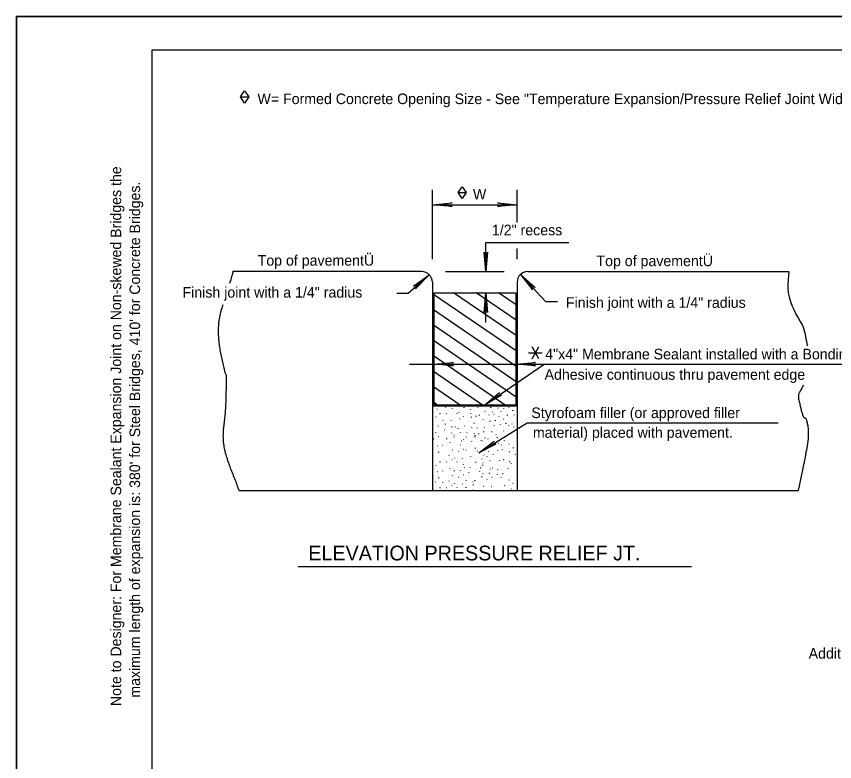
# Model space of a CAD drawing. Extents: x 1000 to 1036, y 1000 to 1022.7.
# Drawn here: x 1000 to 1012.07, y 1011 to 1022 of the extents above; entities that cross this region are included whole.
import ezdxf

# ---------------------------------------------------------------- set-up
doc = ezdxf.new("R2010")
doc.units = 0
for name, color, linetype in [('KS_Borders_Z_N', 7, 'Continuous'), ('KS_PlotShape_z_e', 7, 'Continuous'), ('rd_Detail Annotation_z_n', 7, 'Continuous'), ('rd_Details_z_n', 7, 'Continuous'), ('rd_Dimensions_z_n', 7, 'Continuous'), ('rd_Misc Label_z_n', 7, 'Continuous'), ('rd_Symbols_z_n', 7, 'Continuous')]:
    doc.layers.add(name, color=color, linetype=linetype)

msp = doc.modelspace()

# ---------------------------------------------------------------- linework, layer by layer
at = {"layer": 'KS_Borders_Z_N'}
for points in [[(999.998, 1021.998), (1035.998, 1021.998), (1035.998, 999.998), (999.998, 999.998)], [(1001.998, 1000.498), (1035.498, 1000.498), (1035.498, 1021.498), (1001.998, 1021.498)]]:
    msp.add_lwpolyline(points, close=True, dxfattribs=at)
at = {"layer": 'KS_PlotShape_z_e'}
msp.add_lwpolyline([(999.998, 999.998), (1035.998, 999.998), (1035.998, 1021.998), (999.998, 1021.998)], close=True, dxfattribs=at)
at = {"layer": 'rd_Detail Annotation_z_n'}
for p, q in [((1005.781, 1017.91), (1006.092, 1018.184)), ((1007.806, 1017.791), (1007.438, 1018.189)), ((1005.801, 1016.866), (1012.902, 1016.866)), ((1006.824, 1015.558), (1007.538, 1016)), ((1007.538, 1016), (1011.238, 1016)), ((1004.156, 1013.88), (1009.961, 1013.88))]:
    msp.add_line(p, q, dxfattribs=at)
at = {"layer": 'rd_Details_z_n'}
for p, q in [((1005.981, 1018.23), (1003.195, 1018.23)), ((1007.544, 1018.23), (1011.399, 1018.23)), ((1006.137, 1018.074), (1006.137, 1014.999)), ((1007.387, 1018.074), (1007.387, 1014.999)), ((1007.387, 1017.049), (1006.137, 1017.904)), ((1006.16, 1017.918), (1007.371, 1017.918)), ((1006.16, 1017.918), (1006.16, 1016.266)), ((1007.387, 1017.277), (1006.45, 1017.918)), ((1007.387, 1017.504), (1006.782, 1017.918)), ((1007.387, 1017.731), (1007.114, 1017.918)), ((1007.371, 1017.918), (1007.371, 1016.266)), ((1007.387, 1016.822), (1006.137, 1017.677)), ((1007.387, 1016.595), (1006.137, 1017.45)), ((1007.387, 1016.368), (1006.137, 1017.223)), ((1007.226, 1016.251), (1006.137, 1016.996)), ((1006.894, 1016.251), (1006.137, 1016.768)), ((1006.562, 1016.251), (1006.137, 1016.541)), ((1006.23, 1016.251), (1006.137, 1016.314)), ((1006.137, 1016.251), (1007.387, 1016.251)), ((1006.16, 1016.266), (1007.371, 1016.266)), ((1006.21, 1016.199), (1006.209, 1016.205)), ((1006.335, 1016.219), (1006.334, 1016.226)), ((1006.434, 1016.205), (1006.433, 1016.211)), ((1006.605, 1016.222), (1006.605, 1016.229)), ((1006.701, 1016.19), (1006.701, 1016.197)), ((1006.806, 1016.219), (1006.806, 1016.226)), ((1006.909, 1016.22), (1006.913, 1016.218)), ((1006.914, 1016.164), (1006.913, 1016.17)), ((1006.984, 1016.254), (1006.988, 1016.252)), ((1006.998, 1016.222), (1006.998, 1016.229)), ((1007.108, 1016.216), (1007.108, 1016.222)), ((1007.19, 1016.21), (1007.19, 1016.217)), ((1007.272, 1016.225), (1007.271, 1016.232)), ((1007.324, 1016.178), (1007.324, 1016.185)), ((1006.187, 1016.086), (1006.191, 1016.084)), ((1006.251, 1016.132), (1006.25, 1016.139)), ((1006.348, 1016.137), (1006.353, 1016.135)), ((1006.501, 1016.129), (1006.501, 1016.136)), ((1006.533, 1016.146), (1006.532, 1016.153)), ((1006.543, 1016.053), (1006.542, 1016.059)), ((1006.597, 1016.091), (1006.596, 1016.098)), ((1006.706, 1016.134), (1006.705, 1016.141)), ((1006.717, 1016.078), (1006.716, 1016.085)), ((1006.785, 1016.093), (1006.784, 1016.1)), ((1006.833, 1016.109), (1006.832, 1016.116)), ((1006.886, 1016.041), (1006.886, 1016.048)), ((1006.97, 1016.118), (1006.975, 1016.116)), ((1007.03, 1016.155), (1007.03, 1016.162)), ((1007.046, 1016.126), (1007.05, 1016.121)), ((1007.121, 1016.091), (1007.12, 1016.098)), ((1007.15, 1016.165), (1007.154, 1016.162)), ((1007.187, 1016.056), (1007.191, 1016.054)), ((1007.244, 1016.108), (1007.244, 1016.115)), ((1007.343, 1016.11), (1007.342, 1016.117)), ((1006.227, 1015.947), (1006.226, 1015.954)), ((1006.236, 1015.937), (1006.239, 1015.936)), ((1006.293, 1016.04), (1006.298, 1016.037)), ((1006.333, 1015.975), (1006.332, 1015.982)), ((1006.41, 1016.036), (1006.414, 1016.033)), ((1006.428, 1015.937), (1006.427, 1015.944)), ((1006.474, 1015.942), (1006.478, 1015.939)), ((1006.615, 1015.947), (1006.614, 1015.954)), ((1006.722, 1015.93), (1006.721, 1015.937)), ((1006.756, 1015.991), (1006.755, 1015.998)), ((1006.903, 1015.929), (1006.908, 1015.927)), ((1006.989, 1016.02), (1006.988, 1016.027)), ((1007.05, 1015.953), (1007.049, 1015.96)), ((1007.068, 1016.03), (1007.068, 1016.037)), ((1007.142, 1015.972), (1007.141, 1015.979)), ((1007.225, 1015.986), (1007.225, 1015.993)), ((1007.268, 1015.96), (1007.267, 1015.966)), ((1007.315, 1015.98), (1007.314, 1015.986)), ((1007.34, 1015.935), (1007.339, 1015.942)), ((1006.19, 1015.854), (1006.189, 1015.861)), ((1006.312, 1015.897), (1006.316, 1015.895)), ((1006.418, 1015.85), (1006.423, 1015.848)), ((1006.458, 1015.823), (1006.461, 1015.818)), ((1006.52, 1015.912), (1006.52, 1015.919)), ((1006.55, 1015.856), (1006.55, 1015.863)), ((1006.651, 1015.85), (1006.65, 1015.857)), ((1006.758, 1015.839), (1006.758, 1015.845)), ((1006.768, 1015.808), (1006.767, 1015.815)), ((1006.801, 1015.919), (1006.8, 1015.926)), ((1006.825, 1015.833), (1006.824, 1015.84)), ((1006.898, 1015.863), (1006.897, 1015.87)), ((1007.014, 1015.863), (1007.013, 1015.87)), ((1007.077, 1015.821), (1007.076, 1015.828)), ((1007.18, 1015.915), (1007.184, 1015.913)), ((1007.193, 1015.874), (1007.192, 1015.88)), ((1007.235, 1015.8), (1007.234, 1015.806)), ((1007.297, 1015.843), (1007.296, 1015.85)), ((1006.152, 1015.763), (1006.157, 1015.761)), ((1006.227, 1015.797), (1006.232, 1015.795)), ((1006.352, 1015.758), (1006.351, 1015.765)), ((1006.393, 1015.707), (1006.397, 1015.705)), ((1006.458, 1015.787), (1006.457, 1015.793)), ((1006.564, 1015.734), (1006.568, 1015.732)), ((1006.599, 1015.753), (1006.603, 1015.75)), ((1006.641, 1015.786), (1006.641, 1015.793)), ((1006.721, 1015.721), (1006.72, 1015.728)), ((1006.769, 1015.788), (1006.769, 1015.795)), ((1006.855, 1015.736), (1006.854, 1015.743)), ((1006.877, 1015.726), (1006.876, 1015.733)), ((1006.919, 1015.768), (1006.918, 1015.775)), ((1006.961, 1015.758), (1006.96, 1015.764)), ((1007.098, 1015.779), (1007.097, 1015.785)), ((1007.111, 1015.692), (1007.11, 1015.699)), ((1007.204, 1015.736), (1007.203, 1015.743)), ((1007.271, 1015.684), (1007.27, 1015.691)), ((1006.214, 1015.661), (1006.218, 1015.659)), ((1006.232, 1015.563), (1006.231, 1015.57)), ((1006.289, 1015.669), (1006.293, 1015.664)), ((1006.43, 1015.599), (1006.435, 1015.596)), ((1006.517, 1015.578), (1006.521, 1015.575)), ((1006.554, 1015.669), (1006.553, 1015.676)), ((1006.592, 1015.612), (1006.596, 1015.61)), ((1006.635, 1015.595), (1006.634, 1015.602)), ((1006.776, 1015.622), (1006.775, 1015.629)), ((1006.801, 1015.578), (1006.8, 1015.584)), ((1006.954, 1015.63), (1006.954, 1015.637)), ((1006.969, 1015.571), (1006.968, 1015.578)), ((1007.022, 1015.675), (1007.021, 1015.682)), ((1007.102, 1015.583), (1007.101, 1015.589)), ((1007.155, 1015.668), (1007.154, 1015.675)), ((1007.17, 1015.599), (1007.17, 1015.605)), ((1007.276, 1015.568), (1007.275, 1015.575)), ((1007.334, 1015.626), (1007.333, 1015.633)), ((1006.146, 1015.473), (1006.151, 1015.47)), ((1006.385, 1015.515), (1006.385, 1015.522)), ((1006.423, 1015.458), (1006.428, 1015.456)), ((1006.462, 1015.48), (1006.466, 1015.478)), ((1006.578, 1015.476), (1006.583, 1015.474)), ((1006.705, 1015.497), (1006.704, 1015.504)), ((1006.865, 1015.462), (1006.865, 1015.468)), ((1006.899, 1015.525), (1006.903, 1015.523)), ((1006.945, 1015.496), (1006.945, 1015.503)), ((1006.986, 1015.445), (1006.991, 1015.443)), ((1007.04, 1015.53), (1007.039, 1015.537)), ((1007.135, 1015.436), (1007.134, 1015.443)), ((1007.194, 1015.45), (1007.193, 1015.456)), ((1007.364, 1015.526), (1007.363, 1015.533)), ((1006.187, 1015.373), (1006.191, 1015.37)), ((1006.251, 1015.419), (1006.25, 1015.426)), ((1006.348, 1015.424), (1006.353, 1015.421)), ((1006.393, 1015.328), (1006.397, 1015.326)), ((1006.501, 1015.416), (1006.501, 1015.423)), ((1006.597, 1015.378), (1006.596, 1015.385)), ((1006.609, 1015.333), (1006.608, 1015.339)), ((1006.695, 1015.339), (1006.695, 1015.346)), ((1006.78, 1015.414), (1006.779, 1015.421)), ((1006.852, 1015.331), (1006.852, 1015.338)), ((1006.883, 1015.37), (1006.882, 1015.377)), ((1006.883, 1015.406), (1006.886, 1015.401)), ((1007.024, 1015.336), (1007.028, 1015.334)), ((1007.249, 1015.318), (1007.249, 1015.325)), ((1007.278, 1015.419), (1007.278, 1015.426)), ((1007.305, 1015.396), (1007.304, 1015.402)), ((1006.214, 1015.282), (1006.218, 1015.28)), ((1006.289, 1015.29), (1006.293, 1015.285)), ((1006.43, 1015.22), (1006.435, 1015.217)), ((1006.463, 1015.286), (1006.462, 1015.293)), ((1006.554, 1015.29), (1006.553, 1015.297)), ((1006.592, 1015.233), (1006.596, 1015.231)), ((1006.676, 1015.26), (1006.675, 1015.267)), ((1006.838, 1015.273), (1006.837, 1015.28)), ((1006.868, 1015.199), (1006.867, 1015.206)), ((1006.888, 1015.249), (1006.887, 1015.256)), ((1006.979, 1015.253), (1006.978, 1015.259)), ((1006.989, 1015.318), (1006.993, 1015.316)), ((1007.099, 1015.236), (1007.099, 1015.243)), ((1007.101, 1015.305), (1007.1, 1015.311)), ((1007.177, 1015.243), (1007.176, 1015.249)), ((1006.18, 1015.128), (1006.183, 1015.127)), ((1006.232, 1015.184), (1006.231, 1015.191)), ((1006.293, 1015.116), (1006.292, 1015.123)), ((1006.385, 1015.136), (1006.385, 1015.143)), ((1006.462, 1015.101), (1006.466, 1015.099)), ((1006.517, 1015.198), (1006.521, 1015.196)), ((1006.578, 1015.097), (1006.583, 1015.095)), ((1006.64, 1015.145), (1006.639, 1015.152)), ((1006.74, 1015.123), (1006.739, 1015.13)), ((1006.743, 1015.08), (1006.742, 1015.086)), ((1006.771, 1015.144), (1006.77, 1015.151)), ((1006.942, 1015.161), (1006.946, 1015.159)), ((1007.017, 1015.196), (1007.021, 1015.194)), ((1007.152, 1015.191), (1007.151, 1015.198)), ((1007.269, 1015.15), (1007.269, 1015.157)), ((1007.328, 1015.103), (1007.327, 1015.11)), ((1003.281, 1014.999), (1011.535, 1014.999)), ((1003.281, 1014.999), (1011.137, 1014.999)), ((1006.251, 1015.032), (1006.25, 1015.046)), ((1006.348, 1015.044), (1006.353, 1015.042)), ((1006.423, 1015.079), (1006.428, 1015.077)), ((1006.501, 1015.037), (1006.501, 1015.044)), ((1006.637, 1015.04), (1006.637, 1015.047)), ((1006.738, 1015.004), (1006.737, 1015.011)), ((1006.887, 1015.064), (1006.891, 1015.061)), ((1007.003, 1015.06), (1007.008, 1015.057)), ((1007.205, 1015.066), (1007.204, 1015.073)), ((1007.305, 1015.018), (1007.304, 1015.024))]:
    msp.add_line(p, q, dxfattribs=at)
for centre, start, end in [((1005.981, 1018.074), 0, 90), ((1007.544, 1018.074), 90, 180)]:
    msp.add_arc(centre, 0.156, start, end, dxfattribs=at)
for points in [[(1003.195, 1018.236), (1003.178, 1018.167), (1003.145, 1018.056)], [(1011.399, 1018.23), (1011.391, 1018.156), (1011.385, 1018.069), (1011.384, 1018.026), (1011.384, 1018.005), (1011.384, 1017.983), (1011.393, 1017.898), (1011.599, 1017.437)], [(1003.046, 1017.741), (1003.024, 1017.674), (1002.985, 1017.489), (1002.982, 1017.458), (1002.979, 1017.427), (1002.977, 1017.339), (1002.978, 1017.295), (1002.981, 1017.251), (1002.989, 1017.161), (1003.003, 1017.072), (1003.039, 1016.895), (1003.06, 1016.808), (1003.072, 1016.765), (1003.083, 1016.723), (1003.092, 1016.703)], [(1011.599, 1017.437), (1011.608, 1017.412), (1011.667, 1017.133)], [(1003.092, 1016.703), (1003.06, 1015.97), (1003.052, 1015.905), (1003.05, 1015.872), (1003.048, 1015.84), (1003.048, 1015.776), (1003.049, 1015.744), (1003.05, 1015.728), (1003.051, 1015.72), (1003.051, 1015.716), (1003.052, 1015.712), (1003.058, 1015.666), (1003.066, 1015.621), (1003.076, 1015.576), (1003.088, 1015.531), (1003.116, 1015.442), (1003.147, 1015.353), (1003.217, 1015.176), (1003.251, 1015.088), (1003.281, 1014.999)], [(1011.609, 1016.553), (1011.597, 1016.527), (1011.583, 1016.5), (1011.568, 1016.473), (1011.554, 1016.446), (1011.547, 1016.433), (1011.542, 1016.419), (1011.539, 1016.401), (1011.538, 1016.384), (1011.541, 1016.349), (1011.558, 1016.279), (1011.57, 1016.228), (1011.582, 1016.179), (1011.598, 1016.129), (1011.618, 1016.08), (1011.624, 1016.074), (1011.635, 1016.071), (1011.644, 1016.068), (1011.647, 1016.066), (1011.657, 1016.035), (1011.666, 1016.004), (1011.678, 1015.941), (1011.684, 1015.815), (1011.683, 1015.783), (1011.681, 1015.752), (1011.673, 1015.689), (1011.651, 1015.564), (1011.535, 1014.999)]]:
    msp.add_spline(points, degree=3, dxfattribs=at)
at = {"layer": 'rd_Dimensions_z_n'}
for p, q in [((1006.137, 1018.415), (1006.137, 1019.436)), ((1007.387, 1018.953), (1007.387, 1019.436)), ((1006.137, 1019.218), (1007.387, 1019.218)), ((1006.926, 1018.23), (1006.926, 1018.658)), ((1006.926, 1018.658), (1008.149, 1018.658)), ((1007.387, 1018.415), (1007.387, 1018.57)), ((1006.331, 1018.23), (1007.195, 1018.23)), ((1005.612, 1017.91), (1005.781, 1017.91)), ((1006.926, 1017.478), (1006.926, 1017.918)), ((1007.806, 1017.791), (1007.984, 1017.791)), ((1006.905, 1016.258), (1007.785, 1016.866))]:
    msp.add_line(p, q, dxfattribs=at)
at = {"layer": 'rd_Misc Label_z_n'}
for points in [[(1006.427, 1019.193), (1006.137, 1019.218), (1006.427, 1019.244), (1006.287, 1019.218), (1006.427, 1019.193)], [(1007.098, 1019.244), (1007.387, 1019.218), (1007.098, 1019.193), (1007.237, 1019.218), (1007.098, 1019.244)], [(1006.951, 1018.519), (1006.926, 1018.23), (1006.901, 1018.519), (1006.926, 1018.38), (1006.951, 1018.519)], [(1005.857, 1018.014), (1006.092, 1018.184), (1005.89, 1017.975), (1005.979, 1018.086), (1005.857, 1018.014)], [(1007.654, 1017.995), (1007.438, 1018.189), (1007.617, 1017.961), (1007.541, 1018.08), (1007.654, 1017.995)], [(1006.9, 1017.629), (1006.926, 1017.918), (1006.951, 1017.629), (1006.926, 1017.768), (1006.9, 1017.629)], [(1006.449, 1016.841), (1006.16, 1016.866), (1006.449, 1016.891), (1006.31, 1016.866), (1006.449, 1016.841)], [(1007.66, 1016.841), (1007.371, 1016.866), (1007.66, 1016.891), (1007.521, 1016.866), (1007.66, 1016.841)], [(1007.156, 1016.405), (1006.905, 1016.258), (1007.126, 1016.447), (1007.027, 1016.345), (1007.156, 1016.405)], [(1007.074, 1015.684), (1006.824, 1015.558), (1007.049, 1015.726), (1006.947, 1015.634), (1007.074, 1015.684)]]:
    msp.add_lwpolyline(points, dxfattribs=at)
at = {"layer": 'rd_Symbols_z_n'}
for p, q in [((1007.558, 1017.032), (1007.758, 1017.032)), ((1007.608, 1016.945), (1007.708, 1017.119)), ((1007.708, 1016.945), (1007.608, 1017.119))]:
    msp.add_line(p, q, dxfattribs=at)
for points in [[(1003.306, 1020.809), (1003.367, 1020.899), (1003.429, 1020.809)], [(1006.518, 1019.396), (1006.577, 1019.483), (1006.636, 1019.396)]]:
    msp.add_lwpolyline(points, dxfattribs=at)
for points in [[(1003.306, 1020.809), (1003.429, 1020.809), (1003.367, 1020.719)], [(1006.518, 1019.396), (1006.636, 1019.396), (1006.577, 1019.309)]]:
    msp.add_lwpolyline(points, close=True, dxfattribs=at)

# ---------------------------------------------------------------- texts
at = {"layer": 'rd_Detail Annotation_z_n'}
for s, height, p in [('W= Formed Concrete Opening Size - See "Temperature Expansion/Pressure Relief Joint Width Table".', 0.15628, (1003.556, 1020.703)), ('Top of pavementÜ', 0.15628, (1003.559, 1018.318)), ('Top of pavementÜ', 0.15628, (1008.559, 1018.311)), ('Finish joint with a 1/4" radius', 0.15628, (1002.45, 1017.847)), ('Finish joint with a 1/4" radius', 0.15628, (1008.109, 1017.696)), ('4"x4" Membrane Sealant installed with a Bonding', 0.15628, (1007.803, 1016.935)), ('Adhesive continuous thru pavement edge', 0.15628, (1007.793, 1016.634)), ('Styrofoam filler (or approved filler', 0.15628, (1007.598, 1016.069)), ('material) placed with pavement.', 0.15628, (1007.621, 1015.778)), ('ELEVATION PRESSURE RELIEF JT.', 0.21774, (1004.306, 1013.968)), ('Additional 4"x4" Membrane Sealant piece (thru curb and trimmed) ', 0.15628, (1011.69, 1012.518))]:
    msp.add_text(s, height=height, dxfattribs=at).set_placement(p)
at = {"layer": 'rd_Dimensions_z_n'}
for s, p in [('Note to Designer: For Membrane Sealant Expansion Joint on Non-skewed Bridges the', (1001.545, 1011.818)), ("maximum length of expansion is: 380' for Steel Bridges, 410' for Concrete Bridges.", (1001.824, 1011.942))]:
    msp.add_text(s, height=0.15601, rotation=90, dxfattribs=at).set_placement(p)
for s, height, p in [('W', 0.156, (1006.736, 1019.295)), ('1/2" recess', 0.15628, (1007.016, 1018.766))]:
    msp.add_text(s, height=height, dxfattribs=at).set_placement(p)

doc.saveas('drawing.dxf')
